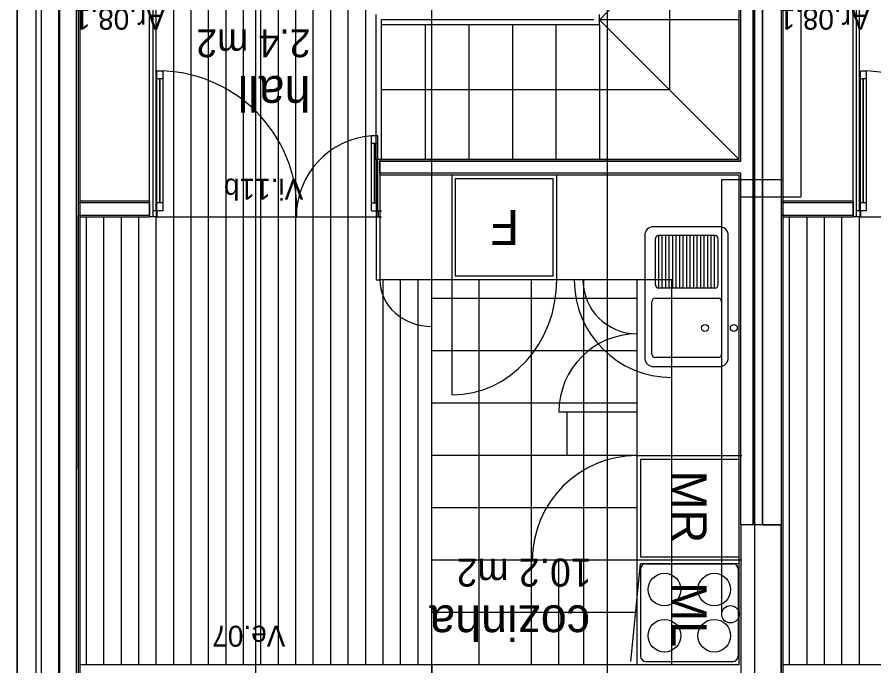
# Model space of a CAD drawing. Extents: x 1248 to 1356, y -443 to -224.
# Drawn here: x 1299.181 to 1304.091, y -243.579 to -239.861 of the extents above; entities that cross this region are included whole.
import ezdxf

# ---------------------------------------------------------------- set-up
doc = ezdxf.new("R2010")
doc.units = 0
for name, color, linetype in [('corte', 7, 'Continuous'), ('estereoctomias', 7, 'Continuous'), ('Level 1', 7, 'Continuous'), ('Level 10', 7, 'Continuous'), ('Level 11', 7, 'Continuous'), ('Level 13', 7, 'Continuous'), ('Level 2', 7, 'Continuous'), ('Level 3', 7, 'Continuous'), ('Level 36', 7, 'Continuous'), ('Level 4', 7, 'Continuous'), ('Level 40', 7, 'Continuous'), ('Level 60', 7, 'Continuous'), ('mob-fixo', 7, 'Continuous'), ('projeccao', 7, 'Continuous'), ('revestimentos', 7, 'Continuous'), ('vermelhos-cont', 7, 'Continuous'), ('vermelhos-tracej', 7, 'Continuous')]:
    doc.layers.add(name, color=color, linetype=linetype)

msp = doc.modelspace()

# ---------------------------------------------------------------- linework, layer by layer
at = {"layer": 'corte'}
for p, q in [((1303.3994, -242.7713), (1303.3994, -238.7963)), ((1299.4227, -238.844), (1299.4227, -243.794)), ((1303.4523, -238.844), (1303.4523, -242.7713)), ((1303.5623, -243.914), (1303.5623, -238.844)), ((1299.5327, -243.914), (1299.5327, -238.914)), ((1303.3294, -240.6863), (1303.3294, -239.0763)), ((1303.3294, -242.7713), (1303.3294, -240.7563))]:
    msp.add_line(p, q, dxfattribs=at)
msp.add_lwpolyline([(1299.519, -238.7263), (1299.519, -243.774), (1299.3208, -243.774), (1299.3208, -238.7263)], dxfattribs=at)
msp.add_lwpolyline([(1303.3294, -243.7713), (1303.5594, -243.7713), (1303.5594, -242.7713), (1303.3294, -242.7713)], close=True, dxfattribs=at)
at = {"layer": 'estereoctomias'}
for points in [[(1299.5327, -238.914), (1299.9827, -238.914), (1299.9827, -238.7263), (1299.519, -238.7263), (1299.519, -238.7963), (1299.9127, -238.7963), (1299.9127, -238.844), (1299.519, -238.844), (1299.519, -243.774), (1299.4227, -243.774), (1299.4227, -243.804), (1299.2908, -243.804), (1299.2908, -238.7963), (1299.3208, -238.7963), (1299.3208, -238.7263), (1299.1808, -238.7263), (1299.1808, -243.914), (1299.519, -243.914), (1299.5327, -243.914), (1299.5304, -240.9963), (1299.9404, -240.9963), (1299.9404, -240.9263), (1299.5327, -240.9263)], [(1303.3994, -242.7713), (1303.3294, -242.7713), (1303.3294, -240.7563), (1301.2594, -240.7563), (1301.2594, -240.6863), (1303.3294, -240.6863), (1303.3294, -238.7963), (1303.5738, -238.7963), (1303.3994, -238.7963), (1303.3994, -242.7713)], [(1303.4519, -242.7713), (1303.5619, -242.7713), (1303.5619, -240.9963), (1303.9719, -240.9963), (1303.9719, -240.9263), (1303.5619, -240.9263), (1303.5619, -238.844), (1303.4519, -238.844)]]:
    msp.add_lwpolyline(points, close=True, dxfattribs=at)
at = {"layer": 'Level 1'}
for p, q in [((1299.1808, -243.914), (1299.1808, -238.7263)), ((1299.2908, -243.794), (1299.2908, -238.7963)), ((1301.2594, -240.6863), (1301.2594, -240.7563)), ((1303.3294, -240.6863), (1301.2594, -240.6863)), ((1303.3294, -240.7563), (1301.2594, -240.7563)), ((1299.9404, -240.9263), (1299.5327, -240.9263)), ((1299.9404, -240.9163), (1299.9404, -241.0063)), ((1303.9719, -240.9263), (1303.5619, -240.9263)), ((1303.9719, -240.9163), (1303.9719, -241.0063)), ((1299.5327, -240.9963), (1299.9404, -240.9963)), ((1303.5619, -240.9963), (1303.9719, -240.9963))]:
    msp.add_line(p, q, dxfattribs=at)
at = {"layer": 'Level 10'}
for p, q in [((1299.9785, -240.9713), (1299.9785, -238.924)), ((1300.0785, -243.574), (1300.0785, -238.924)), ((1300.1785, -243.574), (1300.1785, -238.924)), ((1300.2785, -243.574), (1300.2785, -238.924)), ((1300.3785, -243.574), (1300.3785, -238.924)), ((1300.4785, -243.574), (1300.4785, -238.924)), ((1300.5785, -243.574), (1300.5785, -238.924)), ((1300.6785, -243.574), (1300.6785, -238.924)), ((1300.7785, -243.574), (1300.7785, -238.924)), ((1300.8785, -243.574), (1300.8785, -238.924)), ((1300.9785, -243.574), (1300.9785, -238.924)), ((1301.0785, -243.574), (1301.0785, -238.924)), ((1301.1785, -240.7663), (1301.1785, -238.924)), ((1304.0081, -240.9713), (1304.0081, -238.939)), ((1301.1785, -243.574), (1301.1785, -240.7663)), ((1299.5785, -243.574), (1299.5785, -241.0063)), ((1299.6785, -243.574), (1299.6785, -241.0063)), ((1299.7785, -243.574), (1299.7785, -241.0063)), ((1299.8785, -243.574), (1299.8785, -241.0063)), ((1299.9785, -243.574), (1299.9785, -241.0063)), ((1303.6081, -243.574), (1303.6081, -241.0063)), ((1303.7081, -243.574), (1303.7081, -241.0063)), ((1303.8081, -243.574), (1303.8081, -241.0063)), ((1303.9081, -243.574), (1303.9081, -241.0063)), ((1304.0081, -243.574), (1304.0081, -241.0063)), ((1301.2785, -243.574), (1301.2785, -241.3663)), ((1301.3785, -243.574), (1301.3785, -241.3663)), ((1301.4785, -243.574), (1301.4785, -241.3663)), ((1301.5573, -243.574), (1301.5573, -241.3663)), ((1301.8285, -243.574), (1301.8285, -241.3663)), ((1302.1285, -243.574), (1302.1285, -241.3663)), ((1302.4285, -243.574), (1302.4285, -241.3663)), ((1302.7337, -241.474), (1301.5573, -241.474)), ((1302.7337, -241.774), (1301.5573, -241.774)), ((1302.7337, -242.074), (1301.5573, -242.074)), ((1302.7337, -242.374), (1301.5573, -242.374)), ((1302.7337, -242.674), (1301.5573, -242.674)), ((1302.7337, -242.974), (1301.5573, -242.974)), ((1302.7337, -243.274), (1301.5573, -243.274))]:
    msp.add_line(p, q, dxfattribs=at)
at = {"layer": 'Level 11'}
for p, q in [((1301.6935, -241.3463), (1301.6935, -240.7863)), ((1301.6935, -240.7863), (1302.2535, -240.7863)), ((1302.2535, -241.3463), (1302.2535, -240.7863)), ((1302.8388, -241.3939), (1302.8388, -241.1324)), ((1303.1788, -241.1124), (1302.8588, -241.1124)), ((1302.8588, -241.4139), (1302.8588, -241.1124)), ((1302.8788, -241.4139), (1302.8788, -241.1124)), ((1302.8988, -241.4139), (1302.8988, -241.1124)), ((1302.9188, -241.4139), (1302.9188, -241.1124)), ((1302.9388, -241.4139), (1302.9388, -241.1124)), ((1302.9588, -241.4139), (1302.9588, -241.1124)), ((1302.9788, -241.4139), (1302.9788, -241.1124)), ((1302.9988, -241.4139), (1302.9988, -241.1124)), ((1303.0188, -241.4139), (1303.0188, -241.1124)), ((1303.0388, -241.4139), (1303.0388, -241.1124)), ((1303.0588, -241.4139), (1303.0588, -241.1124)), ((1303.0788, -241.4139), (1303.0788, -241.1124)), ((1303.0988, -241.4139), (1303.0988, -241.1124)), ((1303.1188, -241.4139), (1303.1188, -241.1124)), ((1303.1388, -241.4139), (1303.1388, -241.1124)), ((1303.1588, -241.4139), (1303.1588, -241.1124)), ((1303.1788, -241.4139), (1303.1788, -241.1124)), ((1303.1988, -241.3939), (1303.1988, -241.1324)), ((1302.2535, -241.3463), (1301.6935, -241.3463)), ((1303.1788, -241.4139), (1302.8588, -241.4139)), ((1302.8188, -241.7924), (1302.8188, -241.4924)), ((1302.8388, -241.4724), (1303.1988, -241.4724)), ((1303.2188, -241.4924), (1303.2188, -241.7924)), ((1303.1988, -241.8124), (1302.8388, -241.8124)), ((1302.7837, -242.9939), (1303.2837, -242.9939)), ((1302.7537, -243.0239), (1302.7537, -243.5239)), ((1303.3137, -243.0239), (1303.3137, -243.5239)), ((1302.7837, -243.5539), (1303.2837, -243.5539))]:
    msp.add_line(p, q, dxfattribs=at)
for points in [[(1303.2066, -241.0621), (1302.8282, -241.0621)], [(1302.7782, -241.1121), (1302.7782, -241.8136)], [(1303.2566, -241.8136), (1303.2566, -241.1121)], [(1302.8282, -241.8636), (1303.2066, -241.8636)]]:
    msp.add_lwpolyline(points, dxfattribs=at)
for centre, radius in [((1303.1228, -241.6424), 0.0199), ((1303.2887, -241.6424), 0.0199), ((1302.8911, -243.1417), 0.0936), ((1303.1763, -243.1417), 0.0936), ((1302.8911, -243.406), 0.0936), ((1303.1763, -243.406), 0.0936)]:
    msp.add_circle(centre, radius, dxfattribs=at)
for centre, radius, start, end in [((1302.8282, -241.1121), 0.05, 90, 180), ((1303.2066, -241.1121), 0.05, 0, 90), ((1302.8588, -241.1324), 0.02, 90, 180), ((1303.1788, -241.1324), 0.02, 360, 90), ((1302.8588, -241.3939), 0.02, 180, 270), ((1303.1788, -241.3939), 0.02, 270, 360), ((1302.8388, -241.4924), 0.02, 90, 180), ((1303.1988, -241.4924), 0.02, 360, 90), ((1302.8388, -241.7924), 0.02, 180, 270), ((1303.1988, -241.7924), 0.02, 270, 0), ((1302.8282, -241.8135), 0.05, 180, 270), ((1303.2066, -241.8135), 0.05, 270, 0), ((1302.7837, -243.0239), 0.03, 89.9999, 179.9999), ((1303.2837, -243.0239), 0.03, 359.9998, 90.0001), ((1302.7837, -243.5239), 0.03, 180, 269.9999), ((1303.2837, -243.5239), 0.03, 270, 359.9998)]:
    msp.add_arc(centre, radius, start, end, dxfattribs=at)
at = {"layer": 'Level 13'}
for p, q in [((1299.9404, -241.0063), (1299.9404, -238.9056)), ((1299.9604, -241.0063), (1299.9604, -238.9056)), ((1303.9719, -240.9163), (1303.9719, -238.9056)), ((1303.9919, -241.0063), (1303.9919, -238.9056)), ((1300.0174, -240.1704), (1299.9824, -240.1704)), ((1299.9824, -240.9713), (1299.9824, -240.1704)), ((1300.0174, -240.9713), (1300.0174, -240.1704)), ((1304.0139, -240.9713), (1304.0139, -240.1704)), ((1304.0489, -240.1704), (1304.0139, -240.1704)), ((1304.0489, -240.9713), (1304.0489, -240.1704)), ((1300.0174, -240.2154), (1299.9824, -240.2154)), ((1304.0489, -240.2154), (1304.0139, -240.2154)), ((1301.2474, -240.541), (1301.2124, -240.541)), ((1301.2124, -240.9713), (1301.2124, -240.541)), ((1301.2474, -240.9713), (1301.2474, -240.541)), ((1301.2474, -240.586), (1301.2124, -240.586)), ((1301.2394, -240.6763), (1301.2394, -241.3663)), ((1301.2594, -240.6763), (1301.2394, -240.6763)), ((1301.2594, -240.6763), (1301.2594, -241.3663)), ((1300.0174, -240.9263), (1299.9824, -240.9263)), ((1301.2124, -240.9263), (1301.2474, -240.9263)), ((1304.0489, -240.9263), (1304.0139, -240.9263)), ((1299.9604, -241.0063), (1299.9404, -241.0063)), ((1299.9804, -240.9713), (1299.9604, -240.9713)), ((1299.9804, -240.9713), (1299.9604, -240.9713)), ((1299.9804, -241.0063), (1299.9604, -241.0063)), ((1299.9804, -241.0063), (1299.9604, -241.0063)), ((1299.9804, -241.0063), (1299.9804, -240.9713)), ((1300.0174, -240.9713), (1299.9824, -240.9713)), ((1301.2124, -240.9713), (1301.2474, -240.9713)), ((1301.2494, -240.9713), (1301.2494, -241.0063)), ((1301.2494, -240.9713), (1301.2694, -240.9713)), ((1301.2494, -241.0063), (1301.2694, -241.0063)), ((1303.9919, -241.0063), (1303.9719, -241.0063)), ((1304.0119, -240.9713), (1303.9919, -240.9713)), ((1304.0119, -240.9713), (1303.9919, -240.9713)), ((1304.0119, -241.0063), (1303.9919, -241.0063)), ((1304.0119, -241.0063), (1303.9919, -241.0063)), ((1304.0119, -241.0063), (1304.0119, -240.9713)), ((1304.0489, -240.9713), (1304.0139, -240.9713)), ((1301.2394, -241.3663), (1301.2594, -241.3663))]:
    msp.add_line(p, q, dxfattribs=at)
at = {"layer": 'Level 2'}
for p, q in [((1302.5194, -239.8763), (1303.3194, -239.0763)), ((1302.9194, -239.4763), (1302.9194, -240.2763)), ((1301.2394, -240.6763), (1301.2394, -239.8463)), ((1302.487, -239.8763), (1301.2694, -239.8763)), ((1301.2694, -240.6763), (1301.2694, -239.8763)), ((1302.5194, -239.9063), (1302.5194, -239.8463)), ((1303.3194, -239.8763), (1302.5194, -239.8763)), ((1302.5194, -239.8763), (1303.3194, -240.6763)), ((1302.5194, -239.9063), (1301.2694, -239.9063)), ((1301.5194, -239.9063), (1301.5194, -240.6763)), ((1301.7694, -239.9063), (1301.7694, -240.6763)), ((1302.0194, -239.9063), (1302.0194, -240.6763)), ((1302.2694, -239.9063), (1302.2694, -240.6763)), ((1302.5194, -239.9063), (1302.5194, -240.6763)), ((1301.2694, -240.2763), (1302.9194, -240.2763)), ((1301.6735, -241.3663), (1301.6735, -240.7663)), ((1302.2735, -241.3663), (1302.2735, -240.7663)), ((1302.7337, -241.3663), (1301.2594, -241.3663)), ((1302.7337, -241.3663), (1301.4285, -241.3663)), ((1302.7337, -241.3663), (1301.4285, -241.3663)), ((1302.7337, -243.574), (1302.7337, -241.3663)), ((1301.5573, -243.574), (1299.5427, -243.574)), ((1305.5873, -243.574), (1303.5723, -243.574))]:
    msp.add_line(p, q, dxfattribs=at)
at = {"layer": 'Level 3'}
for p, q in [((1302.9337, -241.3663), (1302.7337, -241.3663)), ((1302.9337, -243.574), (1302.9337, -241.3663))]:
    msp.add_line(p, q, dxfattribs=at)
at = {"layer": 'Level 36'}
for p, q in [((1299.9989, -240.9263), (1299.9989, -240.2154)), ((1300.0009, -240.9263), (1300.0009, -240.2154)), ((1304.0304, -240.9263), (1304.0304, -240.2154)), ((1304.0324, -240.9263), (1304.0324, -240.2154)), ((1301.2289, -240.9263), (1301.2289, -240.586)), ((1301.2309, -240.9263), (1301.2309, -240.586))]:
    msp.add_line(p, q, dxfattribs=at)
at = {"layer": 'Level 4'}
for p, q in [((1301.5573, -241.6339), (1301.5573, -240.7663)), ((1299.9779, -241.0063), (1301.2694, -241.0063)), ((1299.9824, -240.9713), (1299.9824, -241.0063)), ((1301.2474, -240.9713), (1301.2474, -241.0063)), ((1304.0075, -241.0063), (1305.299, -241.0063)), ((1304.0139, -240.9713), (1304.0139, -241.0063)), ((1301.6735, -242.0263), (1301.6735, -241.3663)), ((1302.7337, -242.1243), (1302.2857, -242.1243)), ((1302.3337, -242.374), (1302.3337, -242.1243)), ((1302.7337, -242.374), (1302.2785, -242.374)), ((1302.7337, -242.374), (1303.3337, -242.374)), ((1302.7537, -242.394), (1303.3137, -242.394)), ((1302.7537, -242.394), (1302.7537, -242.954)), ((1302.7537, -242.954), (1303.3137, -242.954)), ((1302.7337, -242.974), (1302.0785, -242.974)), ((1302.2837, -242.974), (1302.2837, -243.574)), ((1302.6985, -243.554), (1302.7537, -242.994)), ((1303.3337, -242.974), (1302.7337, -242.974)), ((1303.3137, -242.994), (1302.7537, -242.994))]:
    msp.add_line(p, q, dxfattribs=at)
for centre, radius, start, end in [((1302.9337, -241.3663), 0.56, 180, 270), ((1302.7337, -241.3663), 0.31, 180, 270), ((1302.7337, -242.1243), 0.448, 90, 180), ((1302.7337, -242.974), 0.6, 90, 180)]:
    msp.add_arc(centre, radius, start, end, dxfattribs=at)
msp.add_ellipse((1301.6735, -241.3663), major_axis=(0, -0.66), ratio=0.909091, start_param=0, end_param=1.570796, dxfattribs=at)
at = {"layer": 'mob-fixo'}
for p, q in [((1303.6719, -238.924), (1303.6719, -240.8913)), ((1303.219, -240.7913), (1303.5719, -240.7913)), ((1303.2194, -243.2833), (1303.2194, -240.7913)), ((1303.319, -240.8913), (1303.6719, -240.8913))]:
    msp.add_line(p, q, dxfattribs=at)
msp.add_circle((1303.2694, -243.2833), 0.05, dxfattribs=at)
at = {"layer": 'projeccao'}
for centre, radius, start, end in [((1299.9881, -240.9656), 0.7962, 357.0703, 87.8908), ((1304.0196, -240.9656), 0.7962, 357.0703, 87.8908), ((1301.2474, -241.0063), 0.4666, 94.3016, 180)]:
    msp.add_arc(centre, radius, start, end, dxfattribs=at)
msp.add_ellipse((1301.5573, -241.3663), major_axis=(-0.2979, 0), ratio=0.898405, start_param=6.283185, end_param=7.853982, dxfattribs=at)
at = {"layer": 'revestimentos'}
for p, q in [((1299.5427, -240.9163), (1299.5427, -238.924)), ((1303.5723, -240.9163), (1303.5723, -238.924)), ((1303.3194, -240.6763), (1303.3194, -239.0763)), ((1303.3194, -240.6763), (1301.2594, -240.6763)), ((1303.3194, -240.7663), (1301.2594, -240.7663)), ((1303.3194, -243.574), (1303.3194, -240.7663)), ((1299.9404, -240.9163), (1299.5427, -240.9163)), ((1303.9719, -240.9163), (1303.5719, -240.9163)), ((1299.5427, -243.924), (1299.5427, -241.0063)), ((1299.5427, -241.0063), (1299.9404, -241.0063)), ((1303.5712, -241.0063), (1303.9719, -241.0063)), ((1303.5723, -243.924), (1303.5723, -241.0063)), ((1303.3194, -243.574), (1301.5573, -243.574)), ((1301.5573, -243.574), (1301.5573, -243.924))]:
    msp.add_line(p, q, dxfattribs=at)
at = {"layer": 'vermelhos-cont'}
for p, q in [((1299.4199, -250.7923), (1299.4199, -225.5674)), ((1303.4094, -250.7923), (1303.4094, -229.6087))]:
    msp.add_line(p, q, dxfattribs=at)
at = {"layer": 'vermelhos-tracej'}
for p, q in [((1299.5423, -246.757), (1299.5423, -236.1407)), ((1300.5498, -246.757), (1300.5498, -236.1407)), ((1301.5573, -246.757), (1301.5573, -236.1407)), ((1302.5648, -246.757), (1302.5648, -236.1407)), ((1303.5723, -246.757), (1303.5723, -236.1407))]:
    msp.add_line(p, q, dxfattribs=at)

# ---------------------------------------------------------------- texts
at = {"layer": 'Level 11'}
for s, rotation, p in [('F', 180, (1302.0574, -240.9663)), ('MR', 270, (1302.9337, -242.4603)), ('ML', 270, (1302.9337, -243.1))]:
    msp.add_text(s, height=0.2, rotation=rotation, dxfattribs=at).set_placement(p)
at = {"layer": 'Level 40'}
for s, p in [('Ar.08.1', (1300.0285, -239.8129)), ('Ar.08.1', (1304.0673, -239.8129)), ('Vi.11b', (1300.8211, -240.7869)), ('Ve.07', (1300.7183, -243.3489))]:
    msp.add_text(s, height=0.12, rotation=180, dxfattribs=at).set_placement(p)
at = {"layer": 'Level 60'}
for s, height, p in [('2.4 m2', 0.16, (1300.8621, -239.9308)), ('hall', 0.2, (1300.8621, -240.1986)), ('10.2 m2', 0.16, (1302.4731, -242.9642)), ('cozinha', 0.2, (1302.4645, -243.232))]:
    msp.add_text(s, height=height, rotation=180, dxfattribs=at).set_placement(p)

doc.saveas('drawing.dxf')
